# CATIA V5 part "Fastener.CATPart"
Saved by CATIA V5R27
Part number: Fastener
Bounding box of the stored display mesh (mm): x -5 to 5, y -4.999 to 4.999, z -48 to 0
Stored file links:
  E:\_Deepak\2017_Deepak\CATIA\Resources\Tutorial Files\Tutorials\c14_catia_v5_6r2016_tut\c14tut2\c14tut2.CATParts\Fastener_cat_v5-6r2016.CATPart
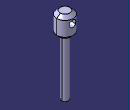
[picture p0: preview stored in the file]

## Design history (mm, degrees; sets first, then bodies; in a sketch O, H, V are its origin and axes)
Body1 (main body)
  Sketch1 on xy-plane, origin (0, 0, 0), H (1, 0, 0), V (0, 1, 0)
    circle A1 centre (0, 0) radius 5
    circle A2 centre (0, 0) radius 2
    radius A2 = 2
    radius A1 = 5
  MultiPad1: profile Sketch1, domains (length 0 / length 48; length 0 / length 13)
  Chamfer1: length 2, angle 45, on 2 edges
  Chamfer2: length 0.508, angle 45, on 1 edge
  Sketch2 on zx-plane, origin (-1.612, 0, 1.612), H (1, 0, 0), V (0, 0, -1)
    point P1 (1.612, 6.35)
    reference intersected line E1 through (1.612, 0) direction (0, 1) from yz-plane
    distance P1 H = 6.35
    coincidence: E1 P1
  Hole1: placed by Sketch2, at (0, 0, -4.738) direction (0, -1, 0), diameter 4, depth 10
